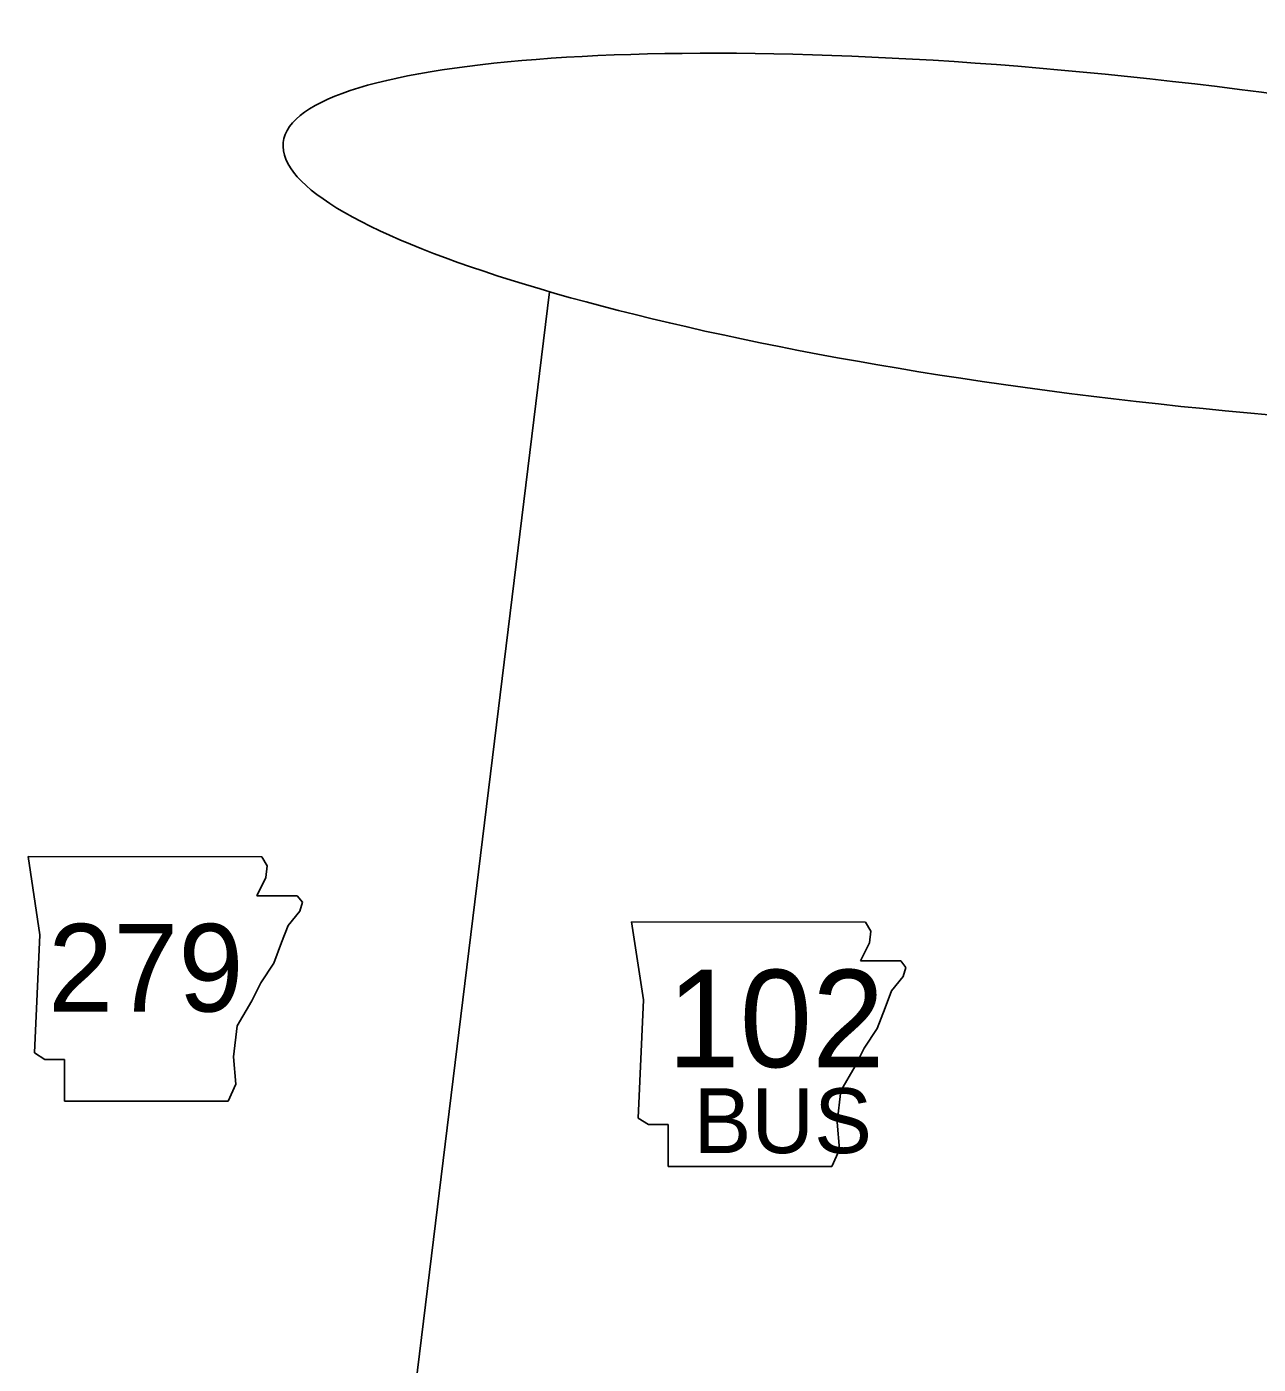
# Model space of a CAD drawing. Extents: x 6028647 to 6035072, y 5366486 to 5368495.
# Drawn here: x 6028934.9 to 6029055.1, y 5368116.1 to 5368246.6 of the extents above; entities that cross this region are included whole.
import ezdxf

# ---------------------------------------------------------------- set-up
doc = ezdxf.new("R2010")
doc.units = 0
for name, color, linetype in [('21', 7, 'Continuous'), ('Default', 7, 'Continuous'), ('Level 1', 7, 'Continuous')]:
    doc.layers.add(name, color=color, linetype=linetype)

msp = doc.modelspace()

# ---------------------------------------------------------------- linework, layer by layer
at = {"layer": '21'}
for p, q in [((6028935.02, 5368165.61), (6028936.16, 5368157.99)), ((6028958.37, 5368164.72), (6028957.84, 5368165.6)), ((6028958.24, 5368163.58), (6028958.37, 5368164.72)), ((6028957.35, 5368161.8), (6028958.24, 5368163.58)), ((6028961.29, 5368161.8), (6028957.35, 5368161.8)), ((6028961.8, 5368161.17), (6028961.29, 5368161.8)), ((6028960.4, 5368158.88), (6028961.54, 5368160.28)), ((6028961.54, 5368160.28), (6028961.8, 5368161.17)), ((6028959.77, 5368157.23), (6028960.4, 5368158.88)), ((6028993.95, 5368159.24), (6028995.09, 5368151.63)), ((6029017.3, 5368158.35), (6029016.77, 5368159.23)), ((6028936.16, 5368157.99), (6028935.66, 5368146.45)), ((6029017.17, 5368157.21), (6029017.3, 5368158.35)), ((6028959, 5368155.2), (6028959.77, 5368157.23)), ((6029016.28, 5368155.43), (6029017.17, 5368157.21)), ((6028957.73, 5368153.3), (6028959, 5368155.2)), ((6029020.22, 5368155.43), (6029016.28, 5368155.43)), ((6029020.72, 5368154.8), (6029020.22, 5368155.43)), ((6029019.33, 5368152.51), (6029020.47, 5368153.91)), ((6029020.47, 5368153.91), (6029020.72, 5368154.8)), ((6028956.85, 5368151.52), (6028957.73, 5368153.3)), ((6029018.69, 5368150.86), (6029019.33, 5368152.51)), ((6028955.45, 5368149.11), (6028956.85, 5368151.52)), ((6028995.09, 5368151.63), (6028994.58, 5368140.08)), ((6029017.93, 5368148.83), (6029018.69, 5368150.86)), ((6028955.07, 5368146.07), (6028955.45, 5368149.11)), ((6029016.66, 5368146.93), (6029017.93, 5368148.83)), ((6028935.66, 5368146.45), (6028936.67, 5368145.81)), ((6028936.67, 5368145.81), (6028938.58, 5368145.81)), ((6028938.58, 5368145.81), (6028938.58, 5368141.75)), ((6028955.32, 5368143.4), (6028955.07, 5368146.07)), ((6029015.77, 5368145.15), (6029016.66, 5368146.93)), ((6029014.38, 5368142.74), (6029015.77, 5368145.15)), ((6028954.56, 5368141.75), (6028955.32, 5368143.4)), ((6028938.58, 5368141.75), (6028954.56, 5368141.75)), ((6029014, 5368139.7), (6029014.38, 5368142.74)), ((6028994.58, 5368140.08), (6028995.6, 5368139.45)), ((6028995.6, 5368139.45), (6028997.5, 5368139.45)), ((6028997.5, 5368139.45), (6028997.5, 5368135.38)), ((6029014.25, 5368137.03), (6029014, 5368139.7)), ((6029013.49, 5368135.38), (6029014.25, 5368137.03)), ((6028997.5, 5368135.38), (6029013.49, 5368135.38))]:
    msp.add_line(p, q, dxfattribs=at)
for points in [[(6028935.02, 5368165.61), (6028957.84, 5368165.6)], [(6028993.95, 5368159.24), (6029016.77, 5368159.23)]]:
    msp.add_lwpolyline(points, dxfattribs=at)
at = {"layer": 'Default'}
msp.add_lwpolyline([(6028985.94, 5368220.75), (6028940.2, 5367847.26), (6028659.63, 5367846.93)], dxfattribs=at)
at = {"layer": 'Level 1'}
msp.add_ellipse((6029044.97, 5368225.67), major_axis=(85.04, -9.66), ratio=0.183736, dxfattribs=at)

# ---------------------------------------------------------------- texts
at = {"layer": '21'}
for s, height, p in [('279', 8.554, (6028936.97, 5368150.49)), ('102', 9.504, (6028997.43, 5368145.06)), ('BUS', 6.336, (6028999.99, 5368136.67))]:
    msp.add_text(s, height=height, dxfattribs=at).set_placement(p)

doc.saveas('drawing.dxf')
